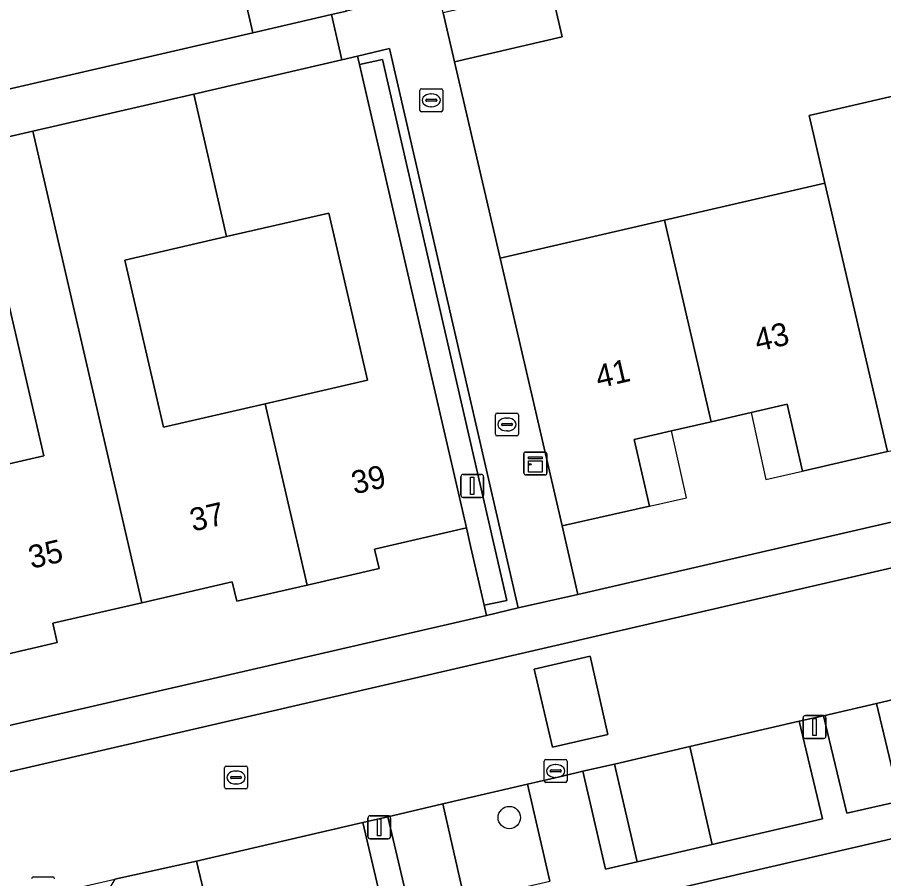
# Model space of a CAD drawing. Extents: x 156412 to 157779, y 382335 to 383768.
# Drawn here: x 156845.13 to 156882.92, y 382762.95 to 382800.53 of the extents above; entities that cross this region are included whole.
import ezdxf

# ---------------------------------------------------------------- set-up
doc = ezdxf.new("R2010")
doc.units = 0
for name, color, linetype in [('IMGEO_Berm_groen', 7, 'Continuous'), ('IMGEO_Boom', 7, 'Continuous'), ('IMGEO_Erf', 7, 'Continuous'), ('IMGEO_Groenvoorziening', 7, 'Continuous'), ('IMGEO_Kast', 7, 'Continuous'), ('IMGEO_Kolk', 7, 'Continuous'), ('IMGEO_Lichtmast', 7, 'Continuous'), ('IMGEO_Muur', 7, 'Continuous'), ('IMGEO_Pand', 7, 'Continuous'), ('IMGEO_Pand_nummerreeks', 7, 'Continuous'), ('IMGEO_Pand_overbouw', 7, 'Continuous'), ('IMGEO_Parkeervlak_open', 7, 'Continuous'), ('IMGEO_Rijbaan_lokaal_gesloten', 7, 'Continuous'), ('IMGEO_Rijbaan_lokaal_open', 7, 'Continuous'), ('IMGEO_Rioolput', 7, 'Continuous'), ('IMGEO_Voetpad_open', 7, 'Continuous')]:
    doc.layers.add(name, color=color, linetype=linetype)

msp = doc.modelspace()

# ---------------------------------------------------------------- linework, layer by layer
at = {"layer": 'IMGEO_Berm_groen'}
for points in [[(156871.181, 382767.957), (156869.802, 382767.638), (156870.783, 382763.369), (156872.159, 382763.684)], [(156867.379, 382767.079), (156863.695, 382766.218), (156864.649, 382761.992), (156868.361, 382762.851)], [(156852.942, 382763.723), (156849.381, 382762.929), (156846.285, 382757.744), (156853.954, 382759.518)]]:
    msp.add_lwpolyline(points, close=True, dxfattribs=at)
at = {"layer": 'IMGEO_Boom'}
msp.add_circle((156866.589, 382765.618), 0.489, dxfattribs=at)
at = {"layer": 'IMGEO_Erf'}
for points in [[(156854.352, 382804.41), (156858.429, 382805.383), (156856.435, 382813.996), (156847.542, 382811.941), (156838.763, 382809.913), (156830.005, 382807.89), (156821.243, 382805.866), (156812.469, 382803.839), (156803.704, 382801.814), (156794.934, 382799.788), (156786.03, 382797.749), (156789.002, 382784.941), (156789.092, 382784.551), (156855.404, 382799.852)], [(156854.258, 382790.964), (156849.824, 382789.94), (156851.508, 382782.646), (156855.942, 382783.669), (156860.401, 382784.698), (156858.718, 382791.993)], [(156840.24, 382787.688), (156835.77, 382786.656), (156837.453, 382779.367), (156841.923, 382780.399), (156846.288, 382781.406), (156844.606, 382788.696)]]:
    msp.add_lwpolyline(points, close=True, dxfattribs=at)
for points in [[(156868.402, 382801.813), (156868.894, 382799.682), (156864.203, 382798.597), (156866.184, 382790.023), (156873.357, 382791.68), (156880.356, 382793.297), (156879.667, 382796.254), (156886.7, 382797.879), (156887.386, 382794.921), (156894.391, 382796.539), (156901.411, 382798.161), (156908.428, 382799.782), (156907.686, 382802.997)], [(156883.083, 382781.596), (156879.383, 382780.731), (156878.706, 382783.656), (156877.134, 382783.293), (156875.396, 382782.892), (156873.666, 382782.493), (156872.034, 382782.116), (156872.709, 382779.2), (156868.89, 382778.342), (156869.58, 382775.359), (156940.042, 382791.626)], [(156943.044, 382778.552), (156872.472, 382762.194), (156872.562, 382761.81), (156873.608, 382757.366), (156874.024, 382757.463), (156874.225, 382756.608), (156876.903, 382757.235), (156876.702, 382758.09), (156881.117, 382759.124), (156881.279, 382758.417), (156882.815, 382758.771), (156883.036, 382758.822), (156882.873, 382759.523), (156886.673, 382760.407)], [(156795.182, 382758.201), (156865.597, 382774.441), (156865.495, 382774.881), (156864.91, 382777.405), (156864.721, 382778.257), (156860.71, 382777.332), (156860.906, 382776.482), (156857.767, 382775.76), (156854.698, 382775.055), (156854.503, 382775.901), (156850.569, 382774.994), (156846.678, 382774.096), (156846.872, 382773.257), (156843.738, 382772.537)]]:
    msp.add_lwpolyline(points, dxfattribs=at)
at = {"layer": 'IMGEO_Groenvoorziening'}
msp.add_lwpolyline([(156865.495, 382774.881), (156866.481, 382775.097), (156861.065, 382798.693), (156860.055, 382798.474), (156864.721, 382778.257), (156864.91, 382777.405)], close=True, dxfattribs=at)
at = {"layer": 'IMGEO_Kast'}
for p, q in [((156867.224, 382780.642), (156867.224, 382781.483)), ((156867.224, 382781.483), (156867.224, 382780.642)), ((156867.299, 382781.567), (156868.14, 382781.567)), ((156868.14, 382781.567), (156867.299, 382781.567)), ((156868.224, 382781.492), (156868.224, 382780.651)), ((156868.224, 382780.651), (156868.224, 382781.492)), ((156868.149, 382780.567), (156867.308, 382780.567)), ((156867.308, 382780.567), (156868.149, 382780.567))]:
    msp.add_line(p, q, dxfattribs=at)
for points in [[(156867.419, 382781.357), (156868.019, 382781.357), (156868.019, 382781.272), (156867.419, 382781.272), (156867.419, 382781.357)], [(156867.419, 382781.182), (156868.019, 382781.182), (156868.019, 382780.693), (156867.419, 382780.693), (156867.419, 382781.182)]]:
    msp.add_lwpolyline(points, dxfattribs=at)
msp.add_circle((156867.503, 382781.031), 0.0377, dxfattribs=at)
for centre, start, end in [((156867.302, 382781.489), 92.4484, 184.2845), ((156867.302, 382781.489), 92.4484, 184.2845), ((156868.146, 382781.489), 2.4484, 94.2845), ((156868.146, 382781.489), 2.4484, 94.2845), ((156867.302, 382780.645), 182.4484, 274.2845), ((156867.302, 382780.645), 182.4484, 274.2845), ((156868.146, 382780.645), 272.4484, 4.2845), ((156868.146, 382780.645), 272.4484, 4.2845)]:
    msp.add_arc(centre, 0.0779, start, end, dxfattribs=at)
at = {"layer": 'IMGEO_Kolk'}
for p, q in [((156862.685, 382796.489), (156862.685, 382797.341)), ((156862.76, 382797.415), (156863.612, 382797.415)), ((156863.686, 382797.341), (156863.686, 382796.489)), ((156862.944, 382796.909), (156862.944, 382796.921)), ((156862.987, 382796.958), (156863.385, 382796.958)), ((156863.173, 382797.195), (156863.198, 382797.195)), ((156863.428, 382796.921), (156863.428, 382796.909)), ((156863.382, 382796.872), (156862.984, 382796.872)), ((156863.196, 382796.635), (156863.171, 382796.635)), ((156863.612, 382796.415), (156862.76, 382796.415)), ((156865.985, 382782.344), (156865.985, 382783.196)), ((156866.06, 382783.27), (156866.912, 382783.27)), ((156866.473, 382783.05), (156866.498, 382783.05)), ((156866.986, 382783.196), (156866.986, 382782.344)), ((156866.244, 382782.764), (156866.244, 382782.776)), ((156866.682, 382782.727), (156866.284, 382782.727)), ((156866.287, 382782.813), (156866.685, 382782.813)), ((156866.728, 382782.776), (156866.728, 382782.764)), ((156866.912, 382782.27), (156866.06, 382782.27)), ((156866.496, 382782.49), (156866.471, 382782.49)), ((156868.111, 382767.228), (156868.111, 382768.08)), ((156868.186, 382768.154), (156869.038, 382768.154)), ((156868.599, 382767.934), (156868.624, 382767.934)), ((156869.112, 382768.08), (156869.112, 382767.228)), ((156868.37, 382767.648), (156868.37, 382767.66)), ((156868.808, 382767.611), (156868.41, 382767.611)), ((156868.413, 382767.697), (156868.811, 382767.697)), ((156868.854, 382767.66), (156868.854, 382767.648)), ((156869.038, 382767.154), (156868.186, 382767.154)), ((156868.622, 382767.374), (156868.597, 382767.374)), ((156845.83, 382763.028), (156846.682, 382763.028))]:
    msp.add_line(p, q, dxfattribs=at)
for points in [[(156862.685, 382796.489), (156862.685, 382797.341)], [(156862.76, 382797.415), (156863.612, 382797.415)], [(156863.686, 382797.341), (156863.686, 382796.489)], [(156863.612, 382796.415), (156862.76, 382796.415)], [(156865.985, 382782.344), (156865.985, 382783.196)], [(156866.06, 382783.27), (156866.912, 382783.27)], [(156866.986, 382783.196), (156866.986, 382782.344)], [(156866.912, 382782.27), (156866.06, 382782.27)], [(156868.111, 382767.228), (156868.111, 382768.08)], [(156868.186, 382768.154), (156869.038, 382768.154)], [(156869.112, 382768.08), (156869.112, 382767.228)], [(156869.038, 382767.154), (156868.186, 382767.154)], [(156845.83, 382763.028), (156846.682, 382763.028)]]:
    msp.add_lwpolyline(points, dxfattribs=at)
for centre, radius, start, end in [((156862.762, 382797.339), 0.0765, 91.552, 178.448), ((156862.762, 382797.339), 0.0765, 91.552, 178.448), ((156863.61, 382797.339), 0.0765, 1.552, 88.448), ((156863.61, 382797.339), 0.0765, 1.552, 88.448), ((156862.984, 382796.918), 0.0403, 85.8775, 175.7526), ((156863.389, 382796.92), 0.0386, 1.7309, 96.639), ((156862.981, 382796.908), 0.0366, 178.938, 274.7102), ((156863.385, 382796.915), 0.043, 264.8664, 352.4533), ((156862.762, 382796.491), 0.0765, 181.552, 268.448), ((156862.762, 382796.491), 0.0765, 181.552, 268.448), ((156863.61, 382796.491), 0.0765, 271.552, 358.448), ((156863.61, 382796.491), 0.0765, 271.552, 358.448), ((156866.062, 382783.194), 0.0765, 91.552, 178.448), ((156866.062, 382783.194), 0.0765, 91.552, 178.448), ((156866.91, 382783.194), 0.0765, 1.552, 88.448), ((156866.91, 382783.194), 0.0765, 1.552, 88.448), ((156866.284, 382782.773), 0.0403, 85.8775, 175.7526), ((156866.281, 382782.763), 0.0366, 178.938, 274.7102), ((156866.685, 382782.77), 0.043, 264.8664, 352.4533), ((156866.689, 382782.775), 0.0386, 1.7309, 96.639), ((156866.062, 382782.346), 0.0765, 181.552, 268.448), ((156866.062, 382782.346), 0.0765, 181.552, 268.448), ((156866.91, 382782.346), 0.0765, 271.552, 358.448), ((156866.91, 382782.346), 0.0765, 271.552, 358.448), ((156868.188, 382768.078), 0.0765, 91.552, 178.448), ((156868.188, 382768.078), 0.0765, 91.552, 178.448), ((156869.036, 382768.078), 0.0765, 1.552, 88.448), ((156869.036, 382768.078), 0.0765, 1.552, 88.448), ((156868.41, 382767.657), 0.0403, 85.8775, 175.7526), ((156868.407, 382767.647), 0.0366, 178.938, 274.7102), ((156868.811, 382767.654), 0.043, 264.8664, 352.4533), ((156868.815, 382767.659), 0.0386, 1.7309, 96.639), ((156868.188, 382767.23), 0.0765, 181.552, 268.448), ((156868.188, 382767.23), 0.0765, 181.552, 268.448), ((156869.036, 382767.23), 0.0765, 271.552, 358.448), ((156869.036, 382767.23), 0.0765, 271.552, 358.448), ((156845.832, 382762.952), 0.0765, 91.552, 178.448), ((156845.832, 382762.952), 0.0765, 91.552, 178.448), ((156846.68, 382762.952), 0.0765, 1.552, 88.448), ((156846.68, 382762.952), 0.0765, 1.552, 88.448)]:
    msp.add_arc(centre, radius, start, end, dxfattribs=at)
for centre, major_axis, ratio, start_param, end_param in [((156863.172, 382796.915), (-0.387, 0.002), 0.722429, 4.712389, 7.853982), ((156863.197, 382796.915), (-0.39, 0.002), 0.717154, 1.570796, 4.712389), ((156866.472, 382782.77), (-0.387, 0.002), 0.722429, 4.712389, 7.853982), ((156866.497, 382782.77), (-0.39, 0.002), 0.717154, 1.570796, 4.712389), ((156868.598, 382767.654), (-0.387, 0.002), 0.722429, 4.712389, 7.853982), ((156868.623, 382767.654), (-0.39, 0.002), 0.717154, 1.570796, 4.712389)]:
    msp.add_ellipse(centre, major_axis=major_axis, ratio=ratio, start_param=start_param, end_param=end_param, dxfattribs=at)
at = {"layer": 'IMGEO_Lichtmast'}
for p, q in [((156864.478, 382779.69), (156864.478, 382780.49)), ((156864.478, 382780.49), (156864.478, 382779.69)), ((156864.578, 382780.59), (156865.368, 382780.59)), ((156865.368, 382780.59), (156864.578, 382780.59)), ((156865.468, 382780.49), (156865.468, 382779.69)), ((156865.468, 382779.69), (156865.468, 382780.49)), ((156865.368, 382779.59), (156864.578, 382779.59)), ((156864.578, 382779.59), (156865.368, 382779.59)), ((156879.405, 382769.172), (156879.405, 382769.972)), ((156879.405, 382769.972), (156879.405, 382769.172)), ((156879.505, 382770.072), (156880.295, 382770.072)), ((156880.295, 382770.072), (156879.505, 382770.072)), ((156880.395, 382769.972), (156880.395, 382769.172)), ((156880.395, 382769.172), (156880.395, 382769.972)), ((156880.295, 382769.072), (156879.505, 382769.072)), ((156879.505, 382769.072), (156880.295, 382769.072)), ((156860.42, 382764.797), (156860.42, 382765.597)), ((156860.42, 382765.597), (156860.42, 382764.797)), ((156860.52, 382765.697), (156861.31, 382765.697)), ((156861.31, 382765.697), (156860.52, 382765.697)), ((156861.41, 382765.597), (156861.41, 382764.797)), ((156861.41, 382764.797), (156861.41, 382765.597)), ((156861.31, 382764.697), (156860.52, 382764.697)), ((156860.52, 382764.697), (156861.31, 382764.697))]:
    msp.add_line(p, q, dxfattribs=at)
for points in [[(156864.898, 382780.465), (156865.048, 382780.465), (156865.048, 382779.715), (156864.898, 382779.715), (156864.898, 382780.465)], [(156879.825, 382769.947), (156879.975, 382769.947), (156879.975, 382769.197), (156879.825, 382769.197), (156879.825, 382769.947)], [(156860.84, 382765.572), (156860.99, 382765.572), (156860.99, 382764.822), (156860.84, 382764.822), (156860.84, 382765.572)]]:
    msp.add_lwpolyline(points, dxfattribs=at)
for centre, start, end in [((156864.578, 382780.49), 90, 180), ((156864.578, 382780.49), 90, 180), ((156865.368, 382780.49), 0, 90), ((156865.368, 382780.49), 360, 90), ((156864.578, 382779.69), 180, 270), ((156864.578, 382779.69), 180, 270), ((156865.368, 382779.69), 270, 0), ((156865.368, 382779.69), 270, 0), ((156879.505, 382769.972), 90, 180), ((156879.505, 382769.972), 90, 180), ((156880.295, 382769.972), 0, 90), ((156880.295, 382769.972), 360, 90), ((156879.505, 382769.172), 180, 270), ((156879.505, 382769.172), 180, 270), ((156880.295, 382769.172), 270, 0), ((156880.295, 382769.172), 270, 0), ((156860.52, 382765.597), 90, 180), ((156860.52, 382765.597), 90, 180), ((156861.31, 382765.597), 0, 90), ((156861.31, 382765.597), 360, 90), ((156860.52, 382764.797), 180, 270), ((156860.52, 382764.797), 180, 270), ((156861.31, 382764.797), 270, 0), ((156861.31, 382764.797), 270, 0)]:
    msp.add_arc(centre, 0.1, start, end, dxfattribs=at)
at = {"layer": 'IMGEO_Muur'}
msp.add_lwpolyline([(156861.369, 382799.171), (156859.972, 382798.832), (156860.055, 382798.474), (156861.065, 382798.693), (156866.481, 382775.097), (156865.495, 382774.881), (156865.597, 382774.441), (156866.975, 382774.768)], close=True, dxfattribs=at)
msp.add_lwpolyline([(156866.184, 382790.023), (156864.203, 382798.597)], dxfattribs=at)
at = {"layer": 'IMGEO_Pand'}
for points in [[(156859.404, 382801.15), (156858.429, 382805.383), (156854.352, 382804.41), (156855.404, 382799.852), (156858.834, 382800.653), (156859.483, 382800.805)], [(156863.704, 382800.728), (156864.203, 382798.597), (156868.894, 382799.682), (156868.402, 382801.813)], [(156860.055, 382798.474), (156859.972, 382798.832), (156859.29, 382798.675), (156852.823, 382797.182), (156854.258, 382790.964), (156858.718, 382791.993), (156860.401, 382784.698), (156855.942, 382783.669), (156857.767, 382775.76), (156860.906, 382776.482), (156860.71, 382777.332), (156864.721, 382778.257)], [(156887.386, 382794.921), (156886.7, 382797.879), (156879.667, 382796.254), (156880.356, 382793.297), (156883.083, 382781.596), (156886.746, 382782.453), (156886.074, 382785.356), (156887.705, 382785.732), (156889.424, 382786.129)], [(156854.258, 382790.964), (156852.823, 382797.182), (156845.81, 382795.564), (156850.569, 382774.994), (156854.503, 382775.901), (156854.698, 382775.055), (156857.767, 382775.76), (156855.942, 382783.669), (156851.508, 382782.646), (156849.824, 382789.94)], [(156845.81, 382795.564), (156838.796, 382793.946), (156840.24, 382787.688), (156844.606, 382788.696), (156846.288, 382781.406), (156841.923, 382780.399), (156843.738, 382772.537), (156846.872, 382773.257), (156846.678, 382774.096), (156850.569, 382774.994)], [(156883.083, 382781.596), (156880.356, 382793.297), (156873.357, 382791.68), (156875.396, 382782.892), (156877.134, 382783.293), (156878.706, 382783.656), (156879.383, 382780.731)], [(156873.357, 382791.68), (156866.184, 382790.023), (156868.89, 382778.342), (156872.709, 382779.2), (156872.034, 382782.116), (156873.666, 382782.493), (156875.396, 382782.892)]]:
    msp.add_lwpolyline(points, close=True, dxfattribs=at)
at = {"layer": 'IMGEO_Pand_overbouw'}
for points in [[(156877.134, 382783.293), (156877.783, 382780.37), (156879.383, 382780.731), (156878.706, 382783.656)], [(156872.709, 382779.2), (156874.321, 382779.565), (156873.666, 382782.493), (156872.034, 382782.116)]]:
    msp.add_lwpolyline(points, close=True, dxfattribs=at)
at = {"layer": 'IMGEO_Parkeervlak_open'}
for points in [[(156882.602, 382770.599), (156880.295, 382770.065), (156881.308, 382765.806), (156883.619, 382766.342)], [(156879.234, 382769.82), (156874.457, 382768.715), (156875.439, 382764.445), (156880.251, 382765.561)], [(156863.695, 382766.218), (156861.297, 382765.657), (156862.285, 382761.446), (156864.649, 382761.992)], [(156860.201, 382765.401), (156852.942, 382763.723), (156853.954, 382759.518), (156861.196, 382761.194)]]:
    msp.add_lwpolyline(points, close=True, dxfattribs=at)
at = {"layer": 'IMGEO_Rijbaan_lokaal_gesloten'}
for points in [[(156940.449, 382789.73), (156830.11, 382764.227), (156721.265, 382739.07)], [(156804.584, 382752.601), (156810.513, 382753.968), (156815.301, 382755.052), (156820.266, 382756.217), (156822.595, 382756.751), (156823.627, 382756.987), (156827.904, 382757.967), (156829.006, 382758.219), (156837.759, 382760.224), (156846.29, 382762.216), (156849.381, 382762.929), (156852.942, 382763.723), (156860.201, 382765.401), (156861.297, 382765.657), (156863.695, 382766.218), (156867.379, 382767.079), (156868.912, 382767.432), (156869.802, 382767.638), (156871.181, 382767.957), (156874.457, 382768.715), (156879.234, 382769.82), (156880.295, 382770.065), (156882.602, 382770.599), (156883.891, 382770.897)]]:
    msp.add_lwpolyline(points, dxfattribs=at)
msp.add_lwpolyline([(156867.672, 382772.088), (156870.117, 382772.668), (156870.881, 382769.25), (156868.47, 382768.687)], close=True, dxfattribs=at)
at = {"layer": 'IMGEO_Rijbaan_lokaal_open'}
for points in [[(156868.47, 382768.687), (156870.881, 382769.25), (156870.117, 382772.668), (156867.672, 382772.088)], [(156874.457, 382768.715), (156871.181, 382767.957), (156872.159, 382763.684), (156875.439, 382764.445)]]:
    msp.add_lwpolyline(points, close=True, dxfattribs=at)
at = {"layer": 'IMGEO_Rioolput'}
for p, q in [((156854.245, 382767.868), (156855.097, 382767.868)), ((156854.17, 382766.942), (156854.17, 382767.794)), ((156854.658, 382767.648), (156854.683, 382767.648)), ((156855.171, 382767.794), (156855.171, 382766.942)), ((156854.429, 382767.362), (156854.429, 382767.374)), ((156854.867, 382767.325), (156854.469, 382767.325)), ((156854.472, 382767.411), (156854.87, 382767.411)), ((156854.681, 382767.088), (156854.656, 382767.088)), ((156854.913, 382767.374), (156854.913, 382767.362)), ((156855.097, 382766.868), (156854.245, 382766.868))]:
    msp.add_line(p, q, dxfattribs=at)
for points in [[(156854.245, 382767.868), (156855.097, 382767.868)], [(156854.17, 382766.942), (156854.17, 382767.794)], [(156855.171, 382767.794), (156855.171, 382766.942)], [(156855.097, 382766.868), (156854.245, 382766.868)]]:
    msp.add_lwpolyline(points, dxfattribs=at)
for centre, radius, start, end in [((156854.247, 382767.792), 0.0765, 91.552, 178.448), ((156854.247, 382767.792), 0.0765, 91.552, 178.448), ((156855.095, 382767.792), 0.0765, 1.552, 88.448), ((156855.095, 382767.792), 0.0765, 1.552, 88.448), ((156854.469, 382767.371), 0.0403, 85.8775, 175.7526), ((156854.466, 382767.361), 0.0366, 178.938, 274.7102), ((156854.87, 382767.368), 0.043, 264.8664, 352.4533), ((156854.874, 382767.373), 0.0386, 1.7309, 96.639), ((156854.247, 382766.944), 0.0765, 181.552, 268.448), ((156854.247, 382766.944), 0.0765, 181.552, 268.448), ((156855.095, 382766.944), 0.0765, 271.552, 358.448), ((156855.095, 382766.944), 0.0765, 271.552, 358.448)]:
    msp.add_arc(centre, radius, start, end, dxfattribs=at)
for centre, major_axis, ratio, start_param, end_param in [((156854.657, 382767.368), (-0.387, 0.002), 0.722429, 4.712389, 7.853982), ((156854.682, 382767.368), (-0.39, 0.002), 0.717154, 1.570796, 4.712389)]:
    msp.add_ellipse(centre, major_axis=major_axis, ratio=ratio, start_param=start_param, end_param=end_param, dxfattribs=at)
at = {"layer": 'IMGEO_Voetpad_open'}
for points in [[(156860.401, 382814.925), (156858.03, 382825.104), (156856.714, 382830.844), (156854.08, 382830.294), (156860.871, 382801.126), (156859.483, 382800.805), (156858.834, 382800.653), (156859.29, 382798.675), (156859.972, 382798.832), (156861.369, 382799.171), (156866.975, 382774.768), (156869.58, 382775.359), (156868.89, 382778.342), (156866.184, 382790.023), (156864.203, 382798.597), (156863.704, 382800.728), (156863.234, 382802.713), (156862.355, 382806.461)], [(156803.731, 382785.854), (156810.743, 382787.473), (156817.756, 382789.091), (156824.77, 382790.709), (156831.783, 382792.327), (156838.796, 382793.946), (156845.81, 382795.564), (156852.823, 382797.182), (156859.29, 382798.675), (156858.834, 382800.653), (156855.404, 382799.852), (156789.092, 382784.551), (156787.72, 382784.234), (156788.095, 382782.246), (156789.549, 382782.582), (156796.717, 382784.236)], [(156830.11, 382764.227), (156940.449, 382789.73), (156940.042, 382791.626), (156869.58, 382775.359), (156866.975, 382774.768), (156865.597, 382774.441), (156795.182, 382758.201), (156793.73, 382757.867), (156791.208, 382757.283), (156759.674, 382750), (156720.792, 382741.02), (156721.265, 382739.07)]]:
    msp.add_lwpolyline(points, close=True, dxfattribs=at)
for points in [[(156807.635, 382747.256), (156812.585, 382748.399), (156819.521, 382750), (156841.91, 382755.169), (156846.252, 382756.171), (156868.702, 382761.353), (156871.125, 382761.892), (156872.472, 382762.194), (156943.044, 382778.552)], [(156883.891, 382770.897), (156882.602, 382770.599), (156883.619, 382766.342), (156881.308, 382765.806), (156880.295, 382770.065), (156879.234, 382769.82), (156880.251, 382765.561), (156875.439, 382764.445), (156872.159, 382763.684), (156870.783, 382763.369), (156869.802, 382767.638), (156868.912, 382767.432), (156867.379, 382767.079), (156868.361, 382762.851)], [(156862.285, 382761.446), (156861.297, 382765.657), (156860.201, 382765.401), (156861.196, 382761.194)]]:
    msp.add_lwpolyline(points, dxfattribs=at)

# ---------------------------------------------------------------- texts
at = {"layer": 'IMGEO_Pand_nummerreeks'}
for s, rotation, p in [('43', 12.9937, (156877.416, 382785.944)), ('41', 12.9937, (156870.48, 382784.343)), ('39', 12.9832, (156859.828, 382779.716)), ('37', 12.9832, (156852.786, 382778.092)), ('35', 12.9832, (156845.744, 382776.468))]:
    msp.add_text(s, height=1, rotation=rotation, dxfattribs=at).set_placement(p)

doc.saveas('drawing.dxf')
